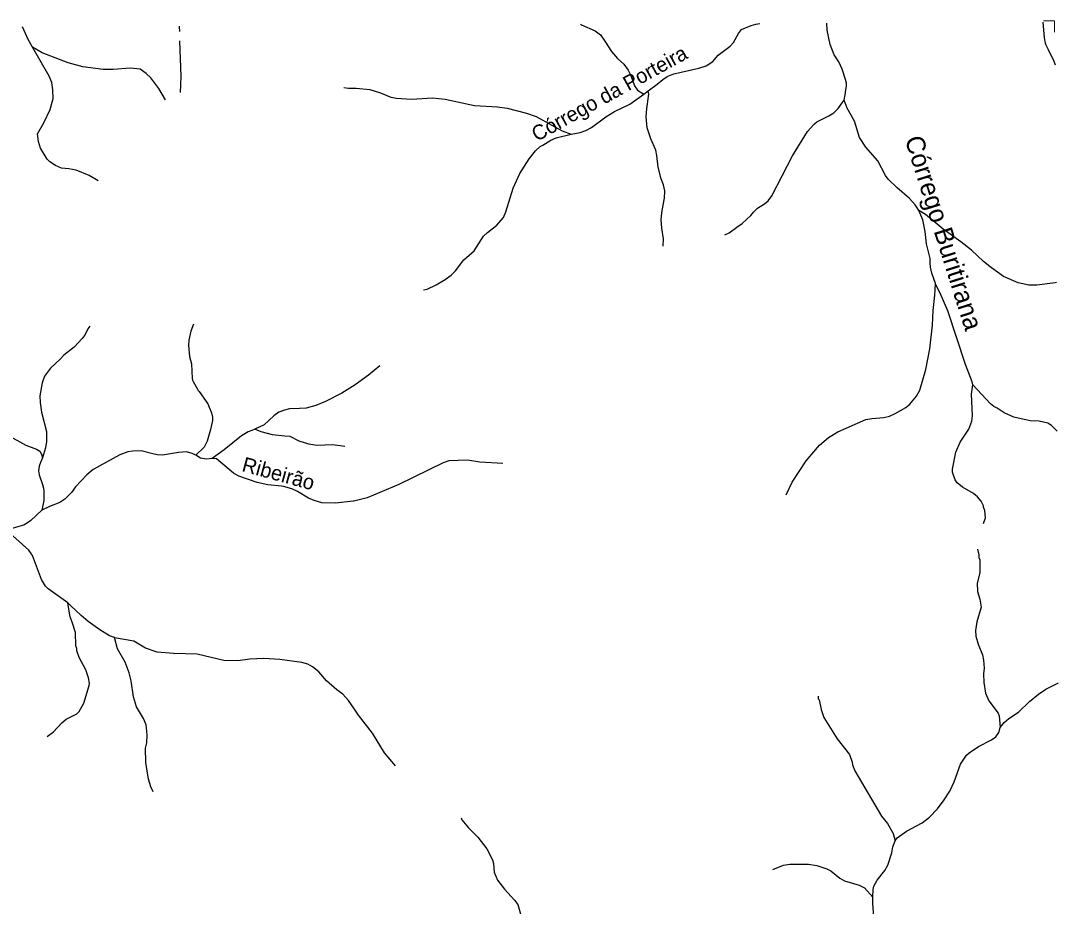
# Model space of a CAD drawing. Extents: x 280.4 to 335.6, y 8893.9 to 8949.5.
# Drawn here: x 324.16 to 335.37, y 8939.96 to 8949.52 of the extents above; entities that cross this region are included whole.
import ezdxf
from ezdxf.enums import TextEntityAlignment as Align

# ---------------------------------------------------------------- set-up
doc = ezdxf.new("R2010")
doc.units = 0
doc.header["$LTSCALE"] = 0.064
doc.linetypes.add('LONG_DASHED', pattern=[7.5, 6, -1.5])
doc.layers.add('61', color=7, linetype='Continuous')
for name, color, linetype, lineweight in [('63', 7, 'Continuous', 13), ('7', 7, 'Continuous', 25), ('9', 7, 'LONG_DASHED', 25)]:
    doc.layers.add(name, color=color, linetype=linetype, lineweight=lineweight)

msp = doc.modelspace()

# ---------------------------------------------------------------- linework, layer by layer
at = {"layer": '63'}
msp.add_lwpolyline([(335.3349, 8949.4008), (335.3349, 8949.524), (335.2135, 8949.524)], dxfattribs=at)
at = {"layer": '7'}
msp.add_line((330.8959, 8948.7316), (330.9433, 8948.7682), dxfattribs=at)
for points in [[(330.2138, 8949.4865), (330.2243, 8949.4817), (330.3718, 8949.4143), (330.43, 8949.3701), (330.4744, 8949.3026), (330.5477, 8949.1912), (330.6113, 8949.1179), (330.6798, 8949.0533), (330.7258, 8948.99), (330.7553, 8948.931), (330.794, 8948.8193), (330.8271, 8948.7756), (330.8959, 8948.7316)], [(330.9433, 8948.7682), (331.042, 8948.8402), (331.1027, 8948.8907), (331.1498, 8948.9227), (331.222, 8948.9493), (331.4924, 8949.0106), (331.5689, 8949.0366), (331.6425, 8949.084), (331.6989, 8949.1534), (331.8302, 8949.2506), (331.8645, 8949.2895), (331.9178, 8949.3859), (331.9521, 8949.4294), (332.0561, 8949.4737), (332.1066, 8949.4854), (332.1486, 8949.495)], [(333.0618, 8948.6675), (333.0694, 8948.7055), (333.074, 8948.7462), (333.0748, 8948.7518), (333.0846, 8948.8195), (333.085, 8948.8511), (333.0751, 8948.8879), (333.0387, 8949.0021), (333.002, 8949.0789), (332.9533, 8949.1573), (332.9098, 8949.2691), (332.8759, 8949.4236), (332.8725, 8949.4964), (332.8724, 8949.4982)], [(335.3451, 8949.0442), (335.3247, 8949.0931), (335.2862, 8949.1701), (335.2677, 8949.2094), (335.2407, 8949.267), (335.2312, 8949.3007), (335.2261, 8949.3419), (335.2106, 8949.506), (335.2104, 8949.5084)], [(327.6566, 8948.8038), (327.706, 8948.7944), (327.7868, 8948.7958), (327.9357, 8948.7801), (328.051, 8948.7451), (328.1641, 8948.6993), (328.225, 8948.6871), (328.3864, 8948.6758), (328.6128, 8948.6917), (328.7512, 8948.6755), (329.0662, 8948.6088), (329.3142, 8948.5926), (329.4188, 8948.5798), (329.6298, 8948.5269), (329.734, 8948.489), (329.9029, 8948.397), (330.0146, 8948.3361), (330.1114, 8948.3005)], [(330.1114, 8948.3005), (330.2097, 8948.3181), (330.2713, 8948.3382), (330.3302, 8948.369), (330.4869, 8948.4871), (330.5808, 8948.5431), (330.7436, 8948.6241), (330.8959, 8948.7316)], [(331.1069, 8947.0894), (331.1083, 8947.1669), (331.0909, 8947.282), (331.0846, 8947.378), (331.0882, 8947.4141), (331.0942, 8947.4732), (331.1197, 8947.6082), (331.1227, 8947.685), (331.1099, 8947.7515), (331.0841, 8947.8171), (331.0497, 8947.9418), (331.0379, 8948.0697), (331.0258, 8948.1242), (330.9707, 8948.248), (330.934, 8948.3663), (330.9231, 8948.4851), (330.9287, 8948.5765), (330.9498, 8948.731), (330.9433, 8948.7682)], [(331.7727, 8947.2125), (331.8183, 8947.2345), (331.9021, 8947.2935), (331.9577, 8947.3326), (332.0531, 8947.4184), (332.0835, 8947.46), (332.1238, 8947.5007), (332.2011, 8947.5457), (332.2397, 8947.5778), (332.2778, 8947.6322), (332.5034, 8948.0654), (332.6659, 8948.3258), (332.734, 8948.4046), (332.7356, 8948.406), (332.767, 8948.4328), (332.8944, 8948.4966), (332.9496, 8948.5308), (332.9965, 8948.5778), (333.0395, 8948.638), (333.0618, 8948.6675)], [(333.8675, 8947.4754), (333.8506, 8947.5017), (333.8267, 8947.5362), (333.7654, 8947.6022), (333.6324, 8947.7176), (333.5382, 8947.8137), (333.509, 8947.8533), (333.4253, 8948.0112), (333.295, 8948.1577), (333.2252, 8948.2617), (333.1734, 8948.4385), (333.0948, 8948.58), (333.0618, 8948.6675)], [(328.5169, 8946.6154), (328.5555, 8946.6232), (328.653, 8946.6701), (328.7515, 8946.7288), (328.8162, 8946.7771), (328.8609, 8946.8236), (328.9522, 8946.9418), (329.063, 8947.0399), (329.1632, 8947.1976), (329.2058, 8947.2381), (329.3094, 8947.3168), (329.3799, 8947.4003), (329.4068, 8947.4589), (329.4834, 8947.7157), (329.556, 8947.8737), (329.6579, 8948.0334), (329.7263, 8948.1204), (329.777, 8948.1645), (329.804, 8948.1814), (329.8909, 8948.2357), (329.9484, 8948.2582), (330.1114, 8948.3005)], [(334.0462, 8946.6864), (334.0091, 8946.7968), (333.9948, 8946.862), (333.9918, 8946.907), (333.9885, 8946.9557), (333.9506, 8947.1134), (333.937, 8947.2458), (333.9101, 8947.3716), (333.8675, 8947.4754)], [(335.3553, 8946.6949), (335.3393, 8946.6929), (335.1427, 8946.6688), (335.0578, 8946.6688), (334.9427, 8946.6927), (334.7827, 8946.7616), (334.6514, 8946.8539), (334.5648, 8946.9243), (334.4357, 8947.0442), (334.3217, 8947.1353), (334.1318, 8947.2732), (333.9391, 8947.43), (333.8675, 8947.4754)], [(332.433, 8944.403), (332.4979, 8944.5396), (332.6487, 8944.7705), (332.7932, 8944.939), (332.89, 8945.0231), (332.9925, 8945.0839), (333.2939, 8945.2148), (333.3594, 8945.2279), (333.4881, 8945.2378), (333.5521, 8945.2525), (333.6118, 8945.2794), (333.7258, 8945.3475), (333.772, 8945.3832), (333.8412, 8945.4671), (333.8774, 8945.5333), (333.9439, 8945.7556), (333.987, 8945.9788), (334.0159, 8946.2354), (334.0239, 8946.3946), (334.0417, 8946.5581), (334.0434, 8946.6174), (334.0462, 8946.6864)], [(334.4521, 8945.5907), (334.4458, 8945.6227), (334.3735, 8945.8104), (334.18, 8946.3905), (334.0994, 8946.5801), (334.0515, 8946.6706), (334.0462, 8946.6864)], [(326.0296, 8946.2476), (326.001, 8946.1705), (325.9813, 8946.0723), (325.9765, 8946.0162), (325.9861, 8945.8956), (326.0085, 8945.8171), (326.0184, 8945.658), (326.0213, 8945.6417), (326.0268, 8945.6262), (326.0734, 8945.5448), (326.0829, 8945.5304), (326.0936, 8945.5183), (326.1843, 8945.3846), (326.2264, 8945.2866), (326.2355, 8945.2431), (326.2352, 8945.207), (326.2221, 8945.1394), (326.2163, 8945.1095), (326.1779, 8944.9816), (326.1448, 8944.9163), (326.0545, 8944.8295)], [(324.9098, 8946.2249), (324.8884, 8946.1973), (324.8597, 8946.1357), (324.8296, 8946.0899), (324.743, 8945.9984), (324.6315, 8945.9123), (324.591, 8945.8671), (324.4862, 8945.7703), (324.4213, 8945.6835), (324.3962, 8945.611), (324.371, 8945.4709), (324.3742, 8945.3999), (324.3896, 8945.2967), (324.4437, 8945.0869), (324.4443, 8944.9792), (324.4321, 8944.911), (324.3993, 8944.8039)], [(328.0458, 8945.7944), (327.9206, 8945.6944), (327.7776, 8945.5917), (327.6353, 8945.5023), (327.4562, 8945.4106), (327.3532, 8945.3663), (327.247, 8945.3391), (327.1767, 8945.3355), (327.0688, 8945.33), (327.0143, 8945.3179), (326.9625, 8945.2977), (326.9546, 8945.2946), (326.9003, 8945.2562), (326.7945, 8945.1604), (326.6924, 8945.1106)], [(334.5662, 8944.0931), (334.5864, 8944.1537), (334.5793, 8944.2321), (334.5649, 8944.2678), (334.5656, 8944.2849), (334.5417, 8944.3329), (334.5032, 8944.3791), (334.4601, 8944.4161), (334.3392, 8944.4836), (334.2826, 8944.5312), (334.2601, 8944.5639), (334.232, 8944.6484), (334.232, 8944.6809), (334.2673, 8944.8647), (334.3158, 8944.9711), (334.4077, 8945.1128), (334.4413, 8945.1992), (334.4492, 8945.2551), (334.4366, 8945.4885), (334.4521, 8945.5907)], [(335.3622, 8945.0901), (335.3512, 8945.1012), (335.3006, 8945.1523), (335.2626, 8945.1769), (335.1672, 8945.1989), (335.0713, 8945.2006), (334.8949, 8945.2399), (334.7912, 8945.2865), (334.7148, 8945.3398), (334.6798, 8945.3559), (334.6433, 8945.3858), (334.4521, 8945.5907)], [(326.6924, 8945.1106), (326.6623, 8945.0959), (326.6227, 8945.0823), (326.5508, 8945.0412), (326.3628, 8944.8884), (326.2333, 8944.7944)], [(327.6665, 8944.9235), (327.5373, 8944.9432), (327.3621, 8944.9369), (327.2783, 8944.9502), (327.1737, 8944.9815), (327.0771, 8945.0313), (327.0189, 8945.037), (326.884, 8945.0501), (326.7627, 8945.0842), (326.6924, 8945.1106)], [(323.409, 8945.007), (323.4335, 8944.9965), (323.5348, 8944.9798), (323.6799, 8944.9689), (323.7719, 8944.9831), (323.8298, 8945.0129), (323.9543, 8945.0533), (324.016, 8945.0524), (324.2198, 8944.9388), (324.3362, 8944.8948), (324.3709, 8944.8738), (324.3877, 8944.8425), (324.3993, 8944.8039)], [(324.3993, 8944.8039), (324.3787, 8944.7511), (324.3619, 8944.7125), (324.3555, 8944.6623), (324.3626, 8944.6194), (324.4011, 8944.5146), (324.4108, 8944.4758), (324.4155, 8944.4435), (324.4155, 8944.3427), (324.3938, 8944.2374)], [(326.0545, 8944.8295), (326.0174, 8944.8504), (325.9547, 8944.8663), (325.8684, 8944.8601), (325.6965, 8944.8313), (325.6367, 8944.8346), (325.5919, 8944.8458), (325.4647, 8944.8776), (325.3768, 8944.8743), (325.3223, 8944.8652), (325.2345, 8944.836), (324.9466, 8944.6777), (324.8793, 8944.6185), (324.7574, 8944.4887), (324.7134, 8944.4269), (324.64, 8944.3567), (324.5883, 8944.3212), (324.4738, 8944.2766), (324.3938, 8944.2374)], [(326.2333, 8944.7944), (326.1715, 8944.7882), (326.1077, 8944.7994), (326.0545, 8944.8295)], [(329.3725, 8944.742), (329.1262, 8944.7559), (328.9901, 8944.7769), (328.7904, 8944.7687), (328.7271, 8944.7481), (328.2512, 8944.515), (327.9068, 8944.3717), (327.7617, 8944.3352), (327.7559, 8944.3346), (327.5636, 8944.3132), (327.4163, 8944.3169), (327.3333, 8944.3401), (327.2737, 8944.3651), (327.1563, 8944.4395), (327.0927, 8944.4682), (327.0036, 8944.4927), (326.9828, 8944.495), (326.8329, 8944.5116), (326.7178, 8944.5356), (326.5197, 8944.6031), (326.4621, 8944.6382), (326.2785, 8944.7901), (326.2499, 8944.7961), (326.2333, 8944.7944)], [(324.3938, 8944.2374), (324.2738, 8944.1234), (324.2047, 8944.0768), (324.0094, 8944.0191)], [(324.6727, 8943.2345), (324.4598, 8943.3877), (324.4337, 8943.4174), (324.3897, 8943.4886), (324.293, 8943.7454), (324.28, 8943.7598), (324.2788, 8943.7701), (324.251, 8943.8042), (324.0094, 8944.0191)], [(334.5003, 8943.8165), (334.5159, 8943.7558), (334.5164, 8943.7249), (334.5261, 8943.701), (334.5259, 8943.5608), (334.4977, 8943.4477), (334.5025, 8943.3593), (334.5263, 8943.2759), (334.5404, 8943.1873), (334.4939, 8943.0289), (334.4814, 8942.9353), (334.4842, 8942.8765), (334.5092, 8942.7901), (334.5546, 8942.6729), (334.5673, 8942.6163), (334.574, 8942.5291), (334.5677, 8942.4683), (334.5694, 8942.3736), (334.5874, 8942.2613), (334.6241, 8942.1759), (334.7239, 8942.0427), (334.736, 8942.016), (334.7473, 8941.8892)], [(324.4506, 8941.7917), (324.5184, 8941.8427), (324.6092, 8941.9382), (324.6565, 8941.9789), (324.7722, 8942.0349), (324.7971, 8942.0624), (324.8444, 8942.15), (324.9051, 8942.3412), (324.908, 8942.3691), (324.8982, 8942.4266), (324.8661, 8942.513), (324.7955, 8942.6469), (324.7709, 8942.7174), (324.7705, 8942.7426), (324.7611, 8942.7707), (324.7543, 8942.9137), (324.721, 8943.0273), (324.6969, 8943.0856), (324.6799, 8943.1902), (324.6727, 8943.2345)], [(325.1758, 8942.8604), (325.1252, 8942.8789), (325.0176, 8942.9437), (324.8922, 8943.0348), (324.8165, 8943.0982), (324.7038, 8943.2083), (324.6891, 8943.2227), (324.6727, 8943.2345)], [(328.2126, 8941.4764), (328.0959, 8941.6153), (327.9658, 8941.8278), (327.8133, 8942.0233), (327.7618, 8942.0994), (327.7057, 8942.1823), (327.6428, 8942.2483), (327.5779, 8942.2941), (327.4675, 8942.3937), (327.3847, 8942.4904), (327.3154, 8942.5432), (327.2648, 8942.5718), (327.1999, 8942.5923), (326.9655, 8942.6241), (326.7906, 8942.6337), (326.6392, 8942.6275), (326.5106, 8942.6084), (326.3577, 8942.6116), (326.0699, 8942.6817), (325.8159, 8942.6883), (325.6401, 8942.7011), (325.512, 8942.7477), (325.3863, 8942.8226), (325.1789, 8942.8593), (325.1758, 8942.8604)], [(325.5969, 8941.1941), (325.57, 8941.2497), (325.5437, 8941.3291), (325.5161, 8941.5098), (325.5127, 8941.664), (325.5253, 8941.723), (325.5319, 8941.8088), (325.5187, 8941.9179), (325.4899, 8941.985), (325.4166, 8942.1113), (325.3817, 8942.2205), (325.356, 8942.3933), (325.3364, 8942.481), (325.2919, 8942.5955), (325.2091, 8942.7388), (325.1758, 8942.8604)], [(334.7473, 8941.8892), (334.7905, 8941.9434), (334.839, 8941.9872), (334.9435, 8942.0534), (335.0625, 8942.1681), (335.162, 8942.248), (335.2417, 8942.3026), (335.369, 8942.3669), (335.3741, 8942.3695)], [(332.7812, 8942.2283), (332.7813, 8942.1991), (332.7895, 8942.188), (332.8119, 8942.0831), (332.8429, 8941.9955), (332.9865, 8941.768), (333.1181, 8941.5984), (333.1465, 8941.5149), (333.1502, 8941.4855), (333.1755, 8941.4218), (333.4642, 8940.9323), (333.5281, 8940.8523), (333.5889, 8940.7451), (333.6124, 8940.6657)], [(333.6124, 8940.6657), (333.6346, 8940.6955), (333.736, 8940.7707), (333.9033, 8940.8599), (333.9823, 8940.9207), (334.0682, 8941.0104), (334.1426, 8941.1057), (334.2018, 8941.2021), (334.2478, 8941.3033), (334.317, 8941.4925), (334.3822, 8941.5895), (334.4115, 8941.6155), (334.5111, 8941.6819), (334.6534, 8941.754), (334.6999, 8941.7877), (334.731, 8941.8348), (334.7473, 8941.8892)], [(328.9247, 8940.9118), (328.9289, 8940.8929), (329.0033, 8940.8049), (329.1019, 8940.7031), (329.2008, 8940.5781), (329.2624, 8940.4604), (329.2726, 8940.4191), (329.2792, 8940.3246), (329.3172, 8940.2386), (329.3905, 8940.1413), (329.5004, 8940.0229), (329.5351, 8939.9752), (329.575, 8939.8369)], [(333.3721, 8940.0544), (333.3729, 8940.1395), (333.3807, 8940.1757), (333.4163, 8940.2414), (333.4989, 8940.3431), (333.5339, 8940.4032), (333.5756, 8940.5341), (333.5861, 8940.6004), (333.6124, 8940.6657)], [(332.2894, 8940.3549), (332.4048, 8940.4026), (332.4733, 8940.4126), (332.6741, 8940.4109), (332.7674, 8940.3971), (332.8732, 8940.3638), (332.9188, 8940.3421), (333.0144, 8940.2613), (333.0653, 8940.2329), (333.2236, 8940.1856), (333.2817, 8940.1581), (333.3721, 8940.0544)], [(333.556, 8939.4573), (333.5411, 8939.4649), (333.4637, 8939.5158), (333.3839, 8939.5924), (333.3657, 8939.6411), (333.3587, 8939.6992), (333.3778, 8939.8927), (333.3715, 8939.988), (333.3721, 8940.0544)]]:
    msp.add_lwpolyline(points, dxfattribs=at)
at = {"layer": '9'}
for points in [[(324.2909, 8949.2386), (324.2442, 8949.3199), (324.1852, 8949.4569), (324.1842, 8949.4591)], [(325.8895, 8948.7473), (325.8966, 8948.9229), (325.8806, 8949.458), (325.8803, 8949.4669)], [(325.7279, 8948.671), (325.6569, 8948.7936), (325.5702, 8948.9061), (325.5192, 8948.9555), (325.4548, 8949.0004), (325.3464, 8949.0132), (325.1613, 8948.999), (325.0552, 8948.999), (324.8353, 8949.0279), (324.676, 8949.0696), (324.3958, 8949.1768), (324.2909, 8949.2386)], [(324.9996, 8947.793), (324.9023, 8947.8535), (324.7626, 8947.9082), (324.6825, 8947.9242), (324.6051, 8947.9311), (324.5409, 8947.9593), (324.479, 8948.0015), (324.4507, 8948.0296), (324.3792, 8948.1459), (324.3563, 8948.2178), (324.3456, 8948.3032), (324.4155, 8948.42), (324.483, 8948.5646), (324.5163, 8948.6823), (324.5114, 8948.7774), (324.4988, 8948.8562), (324.4698, 8948.927), (324.2909, 8949.2386)]]:
    msp.add_lwpolyline(points, dxfattribs=at)

# ---------------------------------------------------------------- texts
at = {"layer": '61'}
for s, height, rotation, p in [('Córrego da Porteira', 0.16, 28.948, (330.5622, 8948.6694)), ('Córrego Buritirana', 0.2, 287.526, (334.0428, 8947.2037)), ('Ribeirão', 0.16, 344.745, (326.9284, 8944.5555))]:
    msp.add_text(s, height=height, rotation=rotation, dxfattribs=at).set_placement(p, align=Align.CENTER)

doc.saveas('drawing.dxf')
